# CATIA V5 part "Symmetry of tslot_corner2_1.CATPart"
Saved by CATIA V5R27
Part number: Symmetry of tslot_corner2_1
Bounding box of the stored display mesh (mm): x -19.05 to 19.05, y -19.05 to 19.05, z -1374.764 to -1219.2
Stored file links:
  \\triton.meca.polymtl.ca\usagers\zaoue\profiles\Desktop\varm_ass\structure prismatique\Symmetry of tslot_corner2_1.CATPart
  \\triton.meca.polymtl.ca\usagers\zaoue\profiles\Desktop\varm_ass\structure prismatique\tslot_corner2.CATPart
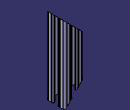
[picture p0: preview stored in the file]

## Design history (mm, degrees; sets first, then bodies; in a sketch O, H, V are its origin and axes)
Body1 (main body)
Body2 "Boss-Extrude1"
  Solid1: linked copy from another document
